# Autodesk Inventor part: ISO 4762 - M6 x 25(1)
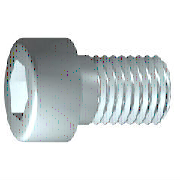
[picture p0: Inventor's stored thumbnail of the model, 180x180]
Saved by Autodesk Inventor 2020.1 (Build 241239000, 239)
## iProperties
Created: 2019-01
Part Number: ISO 4762 - M6 x 25(1)
Material: Edelstahl, 440C
Description: Innensechskantschraube
Document SubType Name: Modeling
Standard: ISO 4762
Designer: lutzd
Standard Revision: Fourth edition 2004-03-01
Standards Organization: ISO
Language: de-DE
Size Designation: M6 x 25
Categories: <MemberInstance><Categories><Category DisplayName="Verbindungselemente" InternalName="e4da775c-781d-43d5-af7c-5136215cf5a6" Mnemonic="FSTN"><Category DisplayNam
Mass: 8.47364 g
Surface Area: 8.58348 cm^2
Volume: 1.09337 cm^3
Density: 7.75 g/cm^3
Appearance: Halbpoliert
IsCustomPart: 0
Author: lutzd
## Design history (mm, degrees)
body "Solid1"
sketch "Skizze1"
  geometry: L1 (-1.333, 0)-(25, 0); L2 (25, 0)-(25, 3); L3 (25, 3)-(2.5, 3); L4 (2.5, 3)-(1.886, 3); L5 (1.886, 3)-(0, 3); L6 (0, 3)-(0, 5); L7 (0, 5)-(-6, 5); L8 (-6, 5)-(-6, 2.887); L9 (-6, 2.887)-(-3, 2.887); L10 (-3, 2.887)-(-1.333, 0); L11 (-12.2, 0)-(31.2, 0) reference; L12 (0, -1)-(0, 6) reference; L13 (2.5, 3)-(0, 3)
  constraints: 22 end point, 6 parallel, 2 collinear, 2 perpendicular, 1 horizontal, 1 point on line
  dimensions: "d1" = 22.5 distance from line of L3.end L2 (= GEL); "d2" = 0.61355 distance of L4.end L3.end (computed from GAL); "d3" = 6 distance between parallel lines of L8 L6 (= KOH); "d4" = 3 distance of L8.end L9.end (= INTI); "d5" = 60 deg angle of L10 L1; "d6" = 6 diameter of L3 L1 (= GD); "d7" = 6 diameter of L5 L1 (= BDM); "d8" = 5.7735 diameter of L9 L1 (= 1.1547 x SW); "d9" = 10 diameter of L7 L1 (= KOD); "d26" = 25 distance between parallel lines of L12 L2 (= NLG)
workplane "Work Plane1"
fillet "Fillet2" dims "d30" = 0.1 (= R)
revolve "Körper" stored, may be unused: angle "d10" = 90 deg
sketch "Skizze2"
  geometry: L1 (0, -7)-(0, 7) reference; L2 (-7, 0)-(7, 0) reference; L3 (2.887, 0)-(1.443, -2.5); L4 (1.443, -2.5)-(-1.443, -2.5); L5 (-1.443, -2.5)-(-2.887, 0); L6 (-2.887, 0)-(-1.443, 2.5); L7 (-1.443, 2.5)-(1.443, 2.5); L8 (1.443, 2.5)-(2.887, 0); 2 further points
  constraints: 12 end point, 1 coincident, 1 horizontal alignment, 1 point on line, 12 other
extrude "Loch" join sketch "Skizze2" stored distance "d11" = 10; taper "d12" = 0 deg
fillet "Rundung1" dims "d17" = 0.6 (= RR)
feature "Gewinde" dims "d13" = 22.5 (= GEL), "d14" = 0
chamfer "Fase1" distance "d15" = 0.61345 (= -0.5 x SPD + 0.5 x GD); stored, may be unused: second distance "d16" = 0.61345 (= GUL), angle "d27" = 45 deg
other parameters: "GD" = 6 [user parameter; used in 2 equation terms], "NLG" = 25 [user parameter; used in 1 equation term], "GEL" = 22.5 [user parameter; used in 2 equation terms], "KOD" = 10 [user parameter; used in 1 equation term], "KOH" = 6 [user parameter; used in 1 equation term], "INTI" = 3 [user parameter; used in 1 equation term], "GAL" = 0.61345 (= 0.61345 x PTC) [user parameter; used in 1 equation term], "GUL" = 0.61345 (= 0.61345 x PTC) [user parameter; used in 1 equation term], "BDM" = 6 (= NND) [user parameter; used in 1 equation term], "SW" = 5 [user parameter; used in 2 equation terms], "RR" = 0.6 [user parameter; used in 1 equation term], "SPD" = 4.7731 (= NND - 1.2269 x PTC) [user parameter; used in 1 equation term], "d19" = 0, "d28" = 0, "d29" = 0, "R" = 0.1 [user parameter; used in 1 equation term], "TOA" = 30 deg [user parameter], "GD1" = 4.7731 (= THREADDIA - 1.2269 x PTC) [user parameter], "THREADDIA" = 6 [user parameter; used in 1 equation term], "FAWI" = 45 deg [user parameter], "PTC" = 1 [user parameter; used in 5 equation terms], "NND" = 6 [user parameter; used in 2 equation terms], "E0" = 5.775 (= 1.155 x SW) [user parameter]
